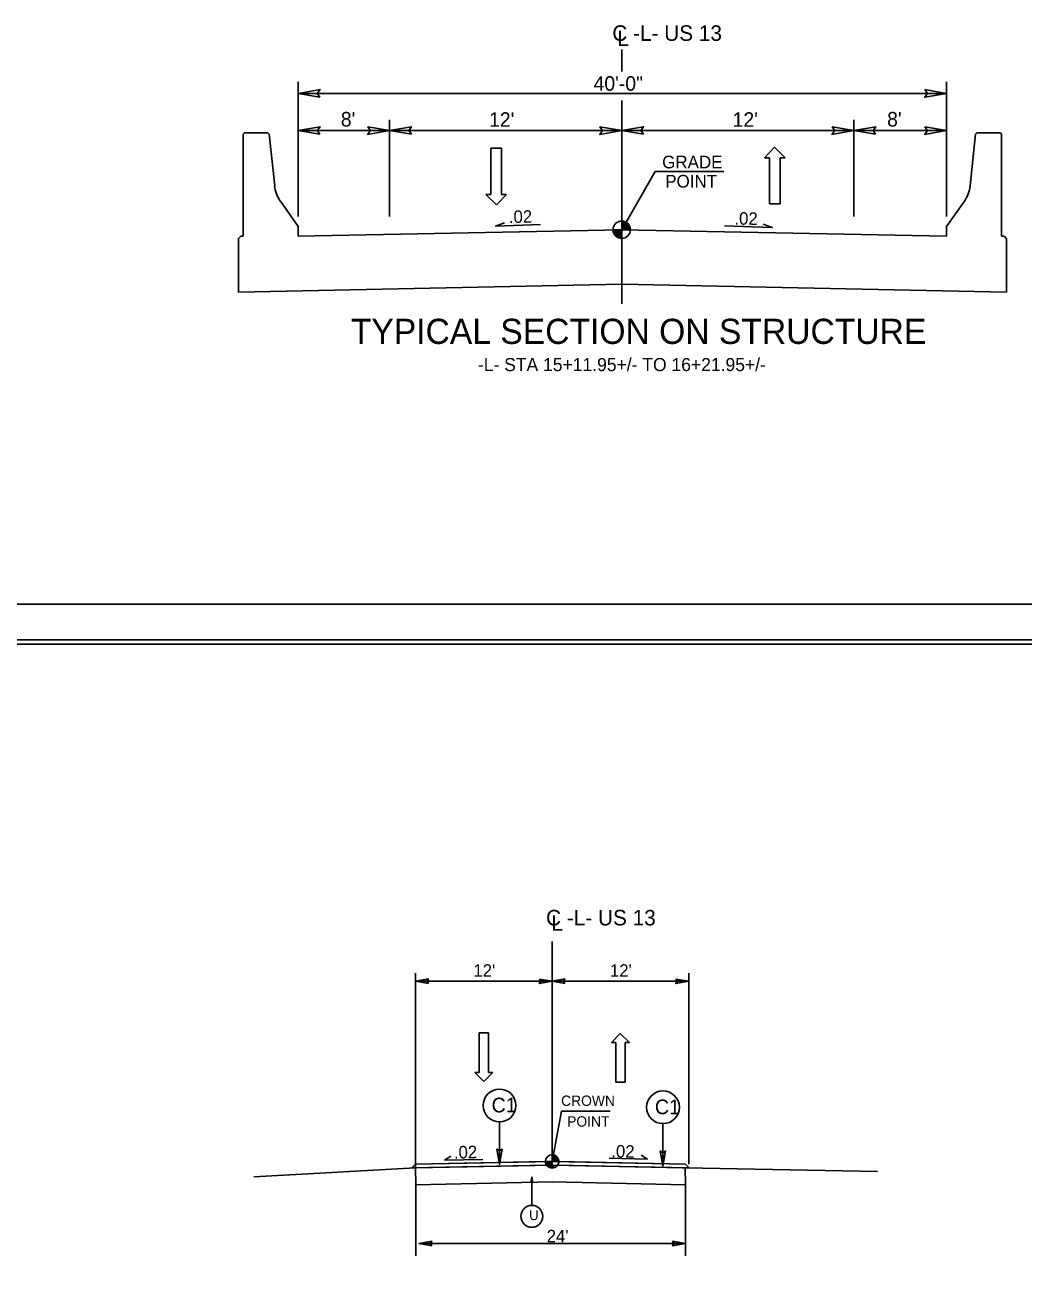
# Model space of a CAD drawing. Extents: x 9470 to 10081, y 10104 to 10463.
# Drawn here: x 9925.2 to 10013, y 10352.7 to 10462.8 of the extents above; entities that cross this region are included whole.
import ezdxf

# ---------------------------------------------------------------- set-up
doc = ezdxf.new("R2010")
doc.units = 0
for name, color, linetype in [('Default', 7, 'Continuous'), ('Old_Level_1', 7, 'Continuous'), ('Old_Level_11', 7, 'Continuous'), ('Old_Level_2', 7, 'Continuous'), ('Old_Level_21', 7, 'Continuous'), ('Old_Level_3', 7, 'Continuous'), ('Old_Level_32', 7, 'Continuous'), ('Old_Level_33', 7, 'Continuous'), ('Prop Dimension Text', 7, 'Continuous'), ('Prop Lane Arrow CELL', 7, 'Continuous'), ('Prop Terminator CELL', 7, 'Continuous'), ('Sheet Cutting Line CELL', 7, 'Continuous'), ('Sheet Plot Border Inside CELL', 7, 'Continuous'), ('Sheet Plot Border Outside CELL', 7, 'Continuous'), ('Sheet Typical CELL', 7, 'Continuous'), ('Typical ID Circle CELL', 7, 'Continuous'), ('Typical Terminator CELL', 7, 'Continuous'), ('Typical Text ID Circle CELL', 7, 'Continuous')]:
    doc.layers.add(name, color=color, linetype=linetype)

msp = doc.modelspace()

# ---------------------------------------------------------------- linework, layer by layer
at = {"layer": 'Default'}
for p, q in [((9966.15, 10447.97), (9966.15, 10452.02)), ((9966.15, 10452.02), (9967.1, 10452.02)), ((9967.1, 10452.02), (9967.1, 10447.97)), ((9990.2, 10451.2), (9991.09, 10452.11)), ((9991.09, 10452.11), (9992.02, 10451.2)), ((9990.63, 10451.2), (9990.2, 10451.2)), ((9990.63, 10447.15), (9990.63, 10451.2)), ((9992.02, 10451.2), (9991.58, 10451.2)), ((9991.58, 10451.2), (9991.58, 10447.15)), ((9966.64, 10447.06), (9965.72, 10447.97)), ((9965.72, 10447.97), (9966.15, 10447.97)), ((9967.54, 10447.97), (9966.64, 10447.06)), ((9967.1, 10447.97), (9967.54, 10447.97)), ((9991.58, 10447.15), (9990.63, 10447.15))]:
    msp.add_line(p, q, dxfattribs=at)
at = {"layer": 'Old_Level_1'}
for p, q in [((9977.66, 10460.7), (9977.66, 10458.76)), ((9949.23, 10457.87), (9949.23, 10446.02)), ((10006.21, 10457.87), (10006.21, 10446.02)), ((9949.23, 10456.85), (10006.21, 10456.85)), ((9977.66, 10456.21), (9977.66, 10438.35)), ((9998.06, 10456.85), (10001.46, 10456.85)), ((9957.26, 10454.51), (9957.26, 10446.02)), ((9998.06, 10454.51), (9998.06, 10446.02)), ((9944.51, 10453.38), (9944.4, 10453.27)), ((9944.4, 10453.27), (9944.4, 10444.3)), ((9946.57, 10453.38), (9944.51, 10453.38)), ((9946.68, 10453.26), (9946.57, 10453.38)), ((9947.16, 10448.72), (9946.68, 10453.26)), ((9949.23, 10453.58), (9957.26, 10453.58)), ((9957.26, 10453.58), (9977.66, 10453.58)), ((9977.66, 10453.58), (9998.06, 10453.58)), ((9998.06, 10453.58), (10006.21, 10453.58)), ((10008.28, 10448.72), (10008.75, 10453.26)), ((10008.75, 10453.26), (10008.87, 10453.38)), ((10008.87, 10453.38), (10010.93, 10453.38)), ((10010.93, 10453.38), (10011.04, 10453.27)), ((10011.04, 10453.27), (10011.04, 10444.3)), ((9977.66, 10444.87), (9980.59, 10449.99)), ((9949.23, 10445.15), (9947.66, 10447.39)), ((10006.21, 10445.15), (10007.78, 10447.39)), ((9977.66, 10444.87), (9977.66, 10445.63)), ((9944.19, 10444.3), (9943.98, 10444.09)), ((9944.4, 10444.3), (9944.19, 10444.3)), ((9949.23, 10444.3), (9949.23, 10445.15)), ((9977.66, 10444.87), (9949.23, 10444.3)), ((9976.89, 10444.87), (9977.66, 10444.87)), ((9978.42, 10444.87), (9977.66, 10444.87)), ((9977.66, 10444.1), (9977.66, 10444.87)), ((9977.66, 10444.87), (9977.66, 10444.1)), ((9977.66, 10444.87), (10006.21, 10444.3)), ((10006.21, 10444.3), (10006.21, 10445.15)), ((10011.04, 10444.3), (10011.25, 10444.3)), ((10011.25, 10444.3), (10011.46, 10444.08)), ((9943.98, 10444.09), (9943.98, 10442.6)), ((10011.46, 10444.08), (10011.46, 10442.6)), ((9943.98, 10442.6), (9943.98, 10439.4)), ((10011.46, 10442.6), (10011.46, 10439.4)), ((9977.66, 10440.08), (9943.98, 10439.4)), ((9977.66, 10440.08), (10011.46, 10439.4)), ((9971.54, 10363.03), (9971.54, 10382.36)), ((9959.54, 10362.46), (9959.54, 10379.56)), ((9983.54, 10362.79), (9983.54, 10379.56)), ((9971.54, 10378.86), (9959.54, 10378.86)), ((9983.54, 10378.86), (9971.54, 10378.86)), ((9971.54, 10362.7), (9959.21, 10362.46)), ((9971.54, 10363.03), (9959.54, 10362.79)), ((9959.54, 10362.46), (9971.54, 10362.7)), ((9970.96, 10363.03), (9971.54, 10363.03)), ((9971.53, 10362.48), (9971.75, 10362.7)), ((9971.54, 10363.03), (9971.54, 10363.61)), ((9972.13, 10363.03), (9971.54, 10363.03)), ((9971.54, 10362.44), (9971.54, 10363.03)), ((9971.54, 10363.03), (9971.54, 10362.44)), ((9971.54, 10363.03), (9983.25, 10362.79)), ((9971.54, 10362.7), (9983.58, 10362.46)), ((9971.54, 10362.7), (9983.24, 10362.47)), ((9983.25, 10362.79), (9983.58, 10362.46)), ((9959.56, 10360.99), (9959.54, 10362.46)), ((9983.24, 10362.47), (9983.25, 10360.98)), ((9983.24, 10362.47), (10000.14, 10362.15)), ((9971.55, 10361.24), (9959.56, 10360.99)), ((9959.56, 10354.75), (9959.56, 10360.99)), ((9983.25, 10360.98), (9971.55, 10361.24)), ((9983.25, 10354.74), (9983.25, 10360.98)), ((9983.25, 10355.82), (9959.85, 10355.82))]:
    msp.add_line(p, q, dxfattribs=at)
for points in [[(9970.53, 10445.32), (9966.57, 10445.19), (9967.35, 10445.48)], [(9977.66, 10445.63), (9977.66, 10445.63), (9977.66, 10444.87)], [(9977.68, 10445.63), (9977.68, 10444.87)], [(9977.69, 10445.63), (9977.69, 10444.87)], [(9977.71, 10445.63), (9977.71, 10444.87)], [(9977.72, 10445.63), (9977.72, 10444.87)], [(9977.74, 10445.63), (9977.74, 10444.87)], [(9977.76, 10445.63), (9977.76, 10444.87)], [(9977.77, 10445.63), (9977.77, 10444.87)], [(9977.79, 10445.62), (9977.79, 10444.87)], [(9977.8, 10445.62), (9977.8, 10444.87)], [(9977.82, 10445.62), (9977.82, 10444.87)], [(9977.83, 10445.61), (9977.83, 10444.87)], [(9977.85, 10445.61), (9977.85, 10444.87)], [(9977.86, 10445.61), (9977.86, 10444.87)], [(9977.88, 10445.6), (9977.88, 10444.87)], [(9977.89, 10445.6), (9977.89, 10444.87)], [(9977.91, 10445.59), (9977.91, 10444.87)], [(9977.92, 10445.59), (9977.92, 10444.87)], [(9977.94, 10445.58), (9977.94, 10444.87)], [(9977.95, 10445.57), (9977.95, 10444.87)], [(9977.97, 10445.57), (9977.97, 10444.87)], [(9977.98, 10445.56), (9977.98, 10444.87)], [(9978, 10445.55), (9978, 10444.87)], [(9978.02, 10445.54), (9978.02, 10444.87)], [(9978.03, 10445.54), (9978.03, 10444.87)], [(9978.05, 10445.53), (9978.05, 10444.87)], [(9978.06, 10445.52), (9978.06, 10444.87)], [(9978.08, 10445.51), (9978.08, 10444.87)], [(9978.09, 10445.5), (9978.09, 10444.87)], [(9978.11, 10445.49), (9978.11, 10444.87)], [(9978.12, 10445.48), (9978.12, 10444.87)], [(9978.14, 10445.46), (9978.14, 10444.87)], [(9978.15, 10445.45), (9978.15, 10444.87)], [(9978.17, 10445.44), (9978.17, 10444.87)], [(9978.18, 10445.42), (9978.18, 10444.87)], [(9978.2, 10445.41), (9978.2, 10444.87)], [(9978.21, 10445.39), (9978.21, 10444.87)], [(9978.23, 10445.38), (9978.23, 10444.87)], [(9978.25, 10445.36), (9978.25, 10444.87)], [(9978.26, 10445.34), (9978.26, 10444.87)], [(9978.28, 10445.32), (9978.28, 10444.87)], [(9978.29, 10445.3), (9978.29, 10444.87)], [(9978.31, 10445.27), (9978.31, 10444.87)], [(9978.32, 10445.25), (9978.32, 10444.87)], [(9978.34, 10445.22), (9978.34, 10444.87)], [(9986.7, 10445.21), (9990.88, 10445.06), (9990.1, 10445.36)], [(9976.9, 10444.87), (9976.9, 10444.79)], [(9976.91, 10444.87), (9976.91, 10444.7)], [(9976.93, 10444.87), (9976.93, 10444.64)], [(9976.94, 10444.87), (9976.94, 10444.6)], [(9976.96, 10444.87), (9976.96, 10444.56)], [(9976.97, 10444.87), (9976.97, 10444.53)], [(9976.99, 10444.87), (9976.99, 10444.5)], [(9977, 10444.87), (9977, 10444.47)], [(9977.02, 10444.87), (9977.02, 10444.45)], [(9977.03, 10444.87), (9977.03, 10444.43)], [(9977.05, 10444.87), (9977.05, 10444.41)], [(9977.06, 10444.87), (9977.06, 10444.39)], [(9977.08, 10444.87), (9977.08, 10444.37)], [(9977.09, 10444.87), (9977.09, 10444.35)], [(9977.11, 10444.87), (9977.11, 10444.33)], [(9977.12, 10444.87), (9977.12, 10444.32)], [(9977.14, 10444.87), (9977.14, 10444.31)], [(9977.16, 10444.87), (9977.16, 10444.29)], [(9977.17, 10444.87), (9977.17, 10444.28)], [(9977.19, 10444.87), (9977.19, 10444.27)], [(9977.2, 10444.87), (9977.2, 10444.25)], [(9977.22, 10444.87), (9977.22, 10444.24)], [(9977.23, 10444.87), (9977.23, 10444.23)], [(9977.25, 10444.87), (9977.25, 10444.22)], [(9977.26, 10444.87), (9977.26, 10444.21)], [(9977.28, 10444.87), (9977.28, 10444.2)], [(9977.29, 10444.87), (9977.29, 10444.2)], [(9977.31, 10444.87), (9977.31, 10444.19)], [(9977.32, 10444.87), (9977.32, 10444.18)], [(9977.34, 10444.87), (9977.34, 10444.17)], [(9977.35, 10444.87), (9977.35, 10444.17)], [(9977.37, 10444.87), (9977.37, 10444.16)], [(9977.38, 10444.87), (9977.38, 10444.15)], [(9977.4, 10444.87), (9977.4, 10444.15)], [(9977.42, 10444.87), (9977.42, 10444.14)], [(9977.43, 10444.87), (9977.43, 10444.14)], [(9977.45, 10444.87), (9977.45, 10444.14)], [(9977.46, 10444.87), (9977.46, 10444.13)], [(9977.48, 10444.87), (9977.48, 10444.13)], [(9977.49, 10444.87), (9977.49, 10444.12)], [(9977.51, 10444.87), (9977.51, 10444.12)], [(9977.52, 10444.87), (9977.52, 10444.12)], [(9977.54, 10444.87), (9977.54, 10444.11)], [(9977.55, 10444.87), (9977.55, 10444.11)], [(9977.57, 10444.87), (9977.57, 10444.11)], [(9977.58, 10444.87), (9977.58, 10444.11)], [(9977.6, 10444.87), (9977.6, 10444.11)], [(9977.61, 10444.87), (9977.61, 10444.11)], [(9977.63, 10444.87), (9977.63, 10444.1)], [(9977.64, 10444.87), (9977.64, 10444.1), (9977.64, 10444.1)], [(9978.35, 10445.19), (9978.35, 10444.87)], [(9978.37, 10445.15), (9978.37, 10444.87)], [(9978.38, 10445.11), (9978.38, 10444.87)], [(9978.4, 10445.06), (9978.4, 10444.87)], [(9978.41, 10444.98), (9978.41, 10444.87)], [(9970.96, 10363.03), (9970.96, 10362.96)], [(9970.97, 10363.03), (9970.97, 10362.89)], [(9970.98, 10363.03), (9970.98, 10362.85)], [(9970.99, 10363.03), (9970.99, 10362.82)], [(9971.01, 10363.03), (9971.01, 10362.79)], [(9971.02, 10363.03), (9971.02, 10362.77)], [(9971.03, 10363.03), (9971.03, 10362.74)], [(9971.04, 10363.03), (9971.04, 10362.72)], [(9971.05, 10363.03), (9971.05, 10362.7)], [(9971.06, 10363.03), (9971.06, 10362.69)], [(9971.08, 10363.03), (9971.08, 10362.67)], [(9971.09, 10363.03), (9971.09, 10362.66)], [(9971.1, 10363.03), (9971.1, 10362.64)], [(9971.11, 10363.03), (9971.11, 10362.63)], [(9971.12, 10363.03), (9971.12, 10362.62)], [(9971.13, 10363.03), (9971.13, 10362.61)], [(9971.15, 10363.03), (9971.15, 10362.6)], [(9971.16, 10363.03), (9971.16, 10362.59)], [(9971.17, 10363.03), (9971.17, 10362.57)], [(9971.18, 10363.03), (9971.18, 10362.57)], [(9971.19, 10363.03), (9971.19, 10362.56)], [(9971.21, 10363.03), (9971.21, 10362.55)], [(9971.22, 10363.03), (9971.22, 10362.54)], [(9971.23, 10363.03), (9971.23, 10362.53)], [(9971.24, 10363.03), (9971.24, 10362.53)], [(9971.25, 10363.03), (9971.25, 10362.52)], [(9971.26, 10363.03), (9971.26, 10362.51)], [(9971.28, 10363.03), (9971.28, 10362.51)], [(9971.29, 10363.03), (9971.29, 10362.5)], [(9971.3, 10363.03), (9971.3, 10362.5)], [(9971.31, 10363.03), (9971.31, 10362.49)], [(9971.32, 10363.03), (9971.32, 10362.48)], [(9971.33, 10363.03), (9971.33, 10362.48)], [(9971.35, 10363.03), (9971.35, 10362.48)], [(9971.36, 10363.03), (9971.36, 10362.47)], [(9971.37, 10363.03), (9971.37, 10362.47)], [(9971.38, 10363.03), (9971.38, 10362.47)], [(9971.39, 10363.03), (9971.39, 10362.46)], [(9971.4, 10363.03), (9971.4, 10362.46)], [(9971.42, 10363.03), (9971.42, 10362.46)], [(9971.43, 10363.03), (9971.43, 10362.45)], [(9971.44, 10363.03), (9971.44, 10362.45)], [(9971.45, 10363.03), (9971.45, 10362.45)], [(9971.46, 10363.03), (9971.46, 10362.45)], [(9971.47, 10363.03), (9971.47, 10362.45)], [(9971.49, 10363.03), (9971.49, 10362.44)], [(9971.5, 10363.03), (9971.5, 10362.44)], [(9971.51, 10363.03), (9971.51, 10362.44)], [(9971.52, 10363.03), (9971.52, 10362.44)], [(9971.53, 10363.03), (9971.53, 10362.44), (9971.53, 10362.44)], [(9971.55, 10363.61), (9971.55, 10363.61), (9971.55, 10363.03)], [(9971.56, 10363.61), (9971.56, 10363.03)], [(9971.57, 10363.61), (9971.57, 10363.03)], [(9971.58, 10363.61), (9971.58, 10363.03)], [(9971.59, 10363.61), (9971.59, 10363.03)], [(9971.61, 10363.61), (9971.61, 10363.03)], [(9971.62, 10363.61), (9971.62, 10363.03)], [(9971.63, 10363.61), (9971.63, 10363.03)], [(9971.64, 10363.6), (9971.64, 10363.03)], [(9971.65, 10363.6), (9971.65, 10363.03)], [(9971.66, 10363.6), (9971.66, 10363.03)], [(9971.68, 10363.6), (9971.68, 10363.03)], [(9971.69, 10363.59), (9971.69, 10363.03)], [(9971.7, 10363.59), (9971.7, 10363.03)], [(9971.71, 10363.59), (9971.71, 10363.03)], [(9971.72, 10363.58), (9971.72, 10363.03)], [(9971.73, 10363.58), (9971.73, 10363.03)], [(9971.75, 10363.58), (9971.75, 10363.03)], [(9971.76, 10363.57), (9971.76, 10363.03)], [(9971.77, 10363.57), (9971.77, 10363.03)], [(9971.78, 10363.56), (9971.78, 10363.03)], [(9971.79, 10363.55), (9971.79, 10363.03)], [(9971.8, 10363.55), (9971.8, 10363.03)], [(9971.82, 10363.54), (9971.82, 10363.03)], [(9971.83, 10363.54), (9971.83, 10363.03)], [(9971.84, 10363.53), (9971.84, 10363.03)], [(9971.85, 10363.52), (9971.85, 10363.03)], [(9971.86, 10363.52), (9971.86, 10363.03)], [(9971.87, 10363.51), (9971.87, 10363.03)], [(9971.89, 10363.5), (9971.89, 10363.03)], [(9971.9, 10363.49), (9971.9, 10363.03)], [(9971.91, 10363.48), (9971.91, 10363.03)], [(9971.92, 10363.47), (9971.92, 10363.03)], [(9971.93, 10363.46), (9971.93, 10363.03)], [(9971.94, 10363.45), (9971.94, 10363.03)], [(9971.96, 10363.44), (9971.96, 10363.03)], [(9971.97, 10363.43), (9971.97, 10363.03)], [(9971.98, 10363.41), (9971.98, 10363.03)], [(9971.99, 10363.4), (9971.99, 10363.03)], [(9972, 10363.39), (9972, 10363.03)], [(9972.02, 10363.37), (9972.02, 10363.03)], [(9972.03, 10363.35), (9972.03, 10363.03)], [(9972.04, 10363.34), (9972.04, 10363.03)], [(9972.05, 10363.32), (9972.05, 10363.03)], [(9972.06, 10363.29), (9972.06, 10363.03)], [(9972.07, 10363.27), (9972.07, 10363.03)], [(9972.09, 10363.24), (9972.09, 10363.03)], [(9972.1, 10363.21), (9972.1, 10363.03)], [(9972.11, 10363.17), (9972.11, 10363.03)], [(9972.12, 10363.11), (9972.12, 10363.03)], [(9945.32, 10361.68), (9959.54, 10362.46)]]:
    msp.add_lwpolyline(points, dxfattribs=at)
for centre, radius in [((9977.66, 10444.87), 0.765), ((9971.54, 10363.03), 0.585)]:
    msp.add_circle(centre, radius, dxfattribs=at)
for centre, radius, start, end in [((9949.98, 10449.02), 2.84, 186.0111, 214.9913), ((10005.45, 10449.01), 2.84, 325.0087, 353.9889), ((9977.66, 10444.87), 0.765, 359.9905, 89.9905), ((9977.66, 10444.87), 0.765, 179.9905, 269.9905), ((9971.54, 10363.03), 0.585, 179.9905, 269.9905), ((9971.54, 10363.03), 0.585, 359.9905, 89.9905)]:
    msp.add_arc(centre, radius, start, end, dxfattribs=at)
at = {"layer": 'Old_Level_11'}
for p, q in [((9972.35, 10367.46), (9971.54, 10363.03)), ((9976.65, 10367.46), (9972.35, 10367.46))]:
    msp.add_line(p, q, dxfattribs=at)
at = {"layer": 'Old_Level_2'}
for p, q in [((9962.07, 10363.14), (9962.63, 10363.48)), ((9962.07, 10363.14), (9965.44, 10363.21)), ((9979.92, 10363.24), (9976.55, 10363.31)), ((9979.92, 10363.24), (9979.36, 10363.58))]:
    msp.add_line(p, q, dxfattribs=at)
at = {"layer": 'Old_Level_21'}
for p, q in [((9959.54, 10362.79), (9959.21, 10362.46)), ((9959.21, 10362.46), (9971.06, 10362.69)), ((9970.96, 10363.02), (9959.54, 10362.79)), ((9983.25, 10362.79), (9972.13, 10363.02)), ((9983.58, 10362.46), (9983.25, 10362.79))]:
    msp.add_line(p, q, dxfattribs=at)
msp.add_lwpolyline([(9972.02, 10362.69), (9982.99, 10362.47), (9983.58, 10362.46)], dxfattribs=at)
for start, end in [(181.0918, 186.1998), (186.1998, 193.0547), (193.0547, 200.9216), (200.9216, 203.8341), (203.8341, 206.5155), (206.5155, 211.3101), (211.3101, 213.4322), (213.4322, 214.8222), (325.1841, 358.9134)]:
    msp.add_arc((9971.54, 10363.03), 0.585, start, end, dxfattribs=at)
at = {"layer": 'Old_Level_3'}
msp.add_line((9980.59, 10449.99), (9986.64, 10449.99), dxfattribs=at)
at = {"layer": 'Old_Level_33'}
msp.add_line((9959.21, 10362.46), (9959.54, 10362.79), dxfattribs=at)
at = {"layer": 'Prop Lane Arrow CELL'}
for p, q in [((9965.13, 10370.84), (9965.13, 10374.34)), ((9965.13, 10374.34), (9965.95, 10374.34)), ((9965.95, 10374.34), (9965.95, 10370.84)), ((9976.75, 10373.49), (9977.53, 10374.28)), ((9977.53, 10374.28), (9978.33, 10373.49)), ((9977.13, 10373.49), (9976.75, 10373.49)), ((9977.13, 10369.99), (9977.13, 10373.49)), ((9978.33, 10373.49), (9977.95, 10373.49)), ((9977.95, 10373.49), (9977.95, 10369.99)), ((9965.55, 10370.05), (9964.75, 10370.84)), ((9964.75, 10370.84), (9965.13, 10370.84)), ((9966.33, 10370.84), (9965.55, 10370.05)), ((9965.95, 10370.84), (9966.33, 10370.84)), ((9977.95, 10369.99), (9977.13, 10369.99))]:
    msp.add_line(p, q, dxfattribs=at)
at = {"layer": 'Prop Terminator CELL'}
for points in [[(9960.67, 10378.66), (9959.54, 10378.86), (9960.67, 10379.06), (9960.53, 10378.86)], [(9970.42, 10379.05), (9971.54, 10378.86), (9970.41, 10378.66), (9970.55, 10378.86)], [(9972.67, 10378.66), (9971.54, 10378.86), (9972.67, 10379.06), (9972.53, 10378.86)], [(9982.42, 10379.05), (9983.54, 10378.86), (9982.41, 10378.66), (9982.55, 10378.86)], [(9960.97, 10355.63), (9959.85, 10355.82), (9960.98, 10356.02), (9960.83, 10355.82)], [(9982.12, 10356.02), (9983.25, 10355.82), (9982.11, 10355.62), (9982.26, 10355.82)]]:
    msp.add_lwpolyline(points, close=True, dxfattribs=at)
at = {"layer": 'Sheet Cutting Line CELL'}
msp.add_line((10052.6, 10411.98), (9816.84, 10411.98), dxfattribs=at)
at = {"layer": 'Sheet Plot Border Inside CELL'}
msp.add_lwpolyline([(10051.97, 10408.84), (9818.66, 10408.84), (9818.66, 10261.13), (10051.97, 10261.13)], close=True, dxfattribs=at)
at = {"layer": 'Sheet Plot Border Outside CELL'}
msp.add_lwpolyline([(10052.6, 10411.98), (9816.84, 10411.98), (9816.84, 10257.98), (10052.6, 10257.98)], close=True, dxfattribs=at)
at = {"layer": 'Sheet Typical CELL'}
msp.add_lwpolyline([(10050.22, 10408.48), (9840.22, 10408.48), (9840.22, 10261.48), (10050.22, 10261.48)], close=True, dxfattribs=at)
at = {"layer": 'Typical ID Circle CELL'}
for p, q in [((9966.92, 10366.51), (9966.92, 10362.78)), ((9981.28, 10366.35), (9981.28, 10362.62)), ((9969.76, 10359.17), (9969.76, 10361.66))]:
    msp.add_line(p, q, dxfattribs=at)
for centre, radius in [((9966.92, 10367.95), 1.44), ((9981.28, 10367.79), 1.44), ((9969.76, 10358.21), 0.962)]:
    msp.add_circle(centre, radius, dxfattribs=at)
at = {"layer": 'Typical Terminator CELL'}
for points in [[(9951.14, 10456.52), (9949.23, 10456.85), (9951.15, 10457.19), (9950.9, 10456.85)], [(10004.3, 10457.18), (10006.21, 10456.85), (10004.29, 10456.51), (10004.53, 10456.85)], [(9951.14, 10453.25), (9949.23, 10453.58), (9951.15, 10453.92), (9950.9, 10453.58)], [(9955.34, 10453.91), (9957.26, 10453.58), (9955.33, 10453.24), (9955.58, 10453.58)], [(9959.17, 10453.25), (9957.26, 10453.58), (9959.18, 10453.92), (9958.94, 10453.58)], [(9975.74, 10453.91), (9977.66, 10453.58), (9975.73, 10453.24), (9975.98, 10453.58)], [(9979.57, 10453.25), (9977.66, 10453.58), (9979.58, 10453.92), (9979.34, 10453.58)], [(9996.14, 10453.91), (9998.06, 10453.58), (9996.13, 10453.24), (9996.38, 10453.58)], [(9999.97, 10453.25), (9998.06, 10453.58), (9999.98, 10453.92), (9999.74, 10453.58)], [(10004.3, 10453.91), (10006.21, 10453.58), (10004.29, 10453.24), (10004.53, 10453.58)], [(9967.15, 10364.12), (9966.92, 10362.78), (9966.69, 10364.12), (9966.92, 10363.95)], [(9981.51, 10363.96), (9981.28, 10362.62), (9981.04, 10363.96), (9981.28, 10363.79)], [(9969.68, 10361.19), (9969.76, 10361.66), (9969.84, 10361.19), (9969.76, 10361.25)]]:
    msp.add_lwpolyline(points, close=True, dxfattribs=at)

# ---------------------------------------------------------------- texts
at = {"layer": 'Old_Level_1'}
for s, height, p in [('C -L- US 13', 1.3647, (9976.83, 10461.46)), ('40\'-0"', 1.275, (9975.18, 10457.08)), ("8'", 1.275, (9952.97, 10453.94)), ("12'", 1.275, (9966, 10453.91)), ("12'", 1.275, (9987.4, 10453.91)), ("8'", 1.275, (10000.98, 10453.94)), ('C -L- US 13', 1.3647, (9971.01, 10383.76))]:
    msp.add_text(s, height=height, dxfattribs=at).set_placement(p)
for p in [(9977.28, 10461), (9971.47, 10383.29)]:
    msp.add_text('L', height=1.37, rotation=359.9469, dxfattribs=at).set_placement(p)
at = {"layer": 'Old_Level_11'}
for s, height, p in [("12'", 1.1, (9964.62, 10379.25)), ("12'", 1.1, (9976.62, 10379.25)), ('CROWN', 0.91, (9972.33, 10367.91)), ('POINT', 0.91, (9972.86, 10366.09)), ("24'", 1.1, (9971.06, 10355.92))]:
    msp.add_text(s, height=height, dxfattribs=at).set_placement(p)
for rotation, p in [(1.1939, (9962.92, 10363.28)), (358.8061, (9976.73, 10363.39))]:
    msp.add_text('.02', height=1.1, rotation=rotation, dxfattribs=at).set_placement(p)
at = {"layer": 'Old_Level_2'}
for rotation, p in [(1.144, (9967.75, 10445.45)), (358.856, (9987.55, 10445.33))]:
    msp.add_text('.02  ', height=1.1, rotation=rotation, dxfattribs=at).set_placement(p)
at = {"layer": 'Old_Level_32'}
for s, height, p in [('TYPICAL SECTION ON STRUCTURE', 2.21, (9953.85, 10434.84)), ('-L- STA 15+11.95+/- TO 16+21.95+/-', 1.15, (9965.02, 10432.45))]:
    msp.add_text(s, height=height, dxfattribs=at).set_placement(p)
at = {"layer": 'Prop Dimension Text'}
for s, p in [('GRADE', (9981.21, 10450.26)), ('POINT', (9981.48, 10448.57))]:
    msp.add_text(s, height=1.115, dxfattribs=at).set_placement(p)
at = {"layer": 'Typical Text ID Circle CELL'}
for s, height, p in [('C1', 1.291, (9966.22, 10367.34)), ('C1', 1.291, (9980.57, 10367.18)), ('U', 0.861, (9969.52, 10357.88))]:
    msp.add_text(s, height=height, dxfattribs=at).set_placement(p)

doc.saveas('drawing.dxf')
